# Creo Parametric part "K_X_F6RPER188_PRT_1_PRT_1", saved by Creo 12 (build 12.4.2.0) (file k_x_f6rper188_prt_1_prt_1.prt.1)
Units: Custom; MM, KILOGRAM, SECS

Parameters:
  PTC_WM_ITERATION = "0"
  PTC_WM_VERSION = "-.0"
  PTC_WM_LIFECYCLE_STATE = "In Work"
  PTC_WM_LIFECYCLE = "MO_CADDocument"
  PTC_WM_CREATED_BY = "Maximilian Roepper (Z0017RMS: MO)"
  PTC_WM_CREATED_ON = "18-Sep-26 11:36:42 AM"
  PTC_WM_MODIFIED_BY = "Maximilian Roepper (Z0017RMS: MO)"
  PTC_WM_MODIFIED_ON = "18-Sep-26 11:36:46 AM"
  PDMLINKNUMBER = "PDM000071455099"
  PTC_WM_NAME = "k_x_f6rper188_prt_1_prt_1.prt"
  PTC_WM_NUMBER = "PDM000071455099"

Other parameters: WEIGHT, WEIGHT_FACTOR, WEIGHT_ADD, _MASS_TEMP, _DIFF_TEMP, MC_ERRORS, SUPPLIER

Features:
  1. coordinate system
  2. datum plane "PRT_YZ"
  3. datum plane "PRT_XY"
  4. datum plane "PRT_XZ"
  5. coordinate system
  6. datum axis
  7. datum axis
  8. datum axis
  9. coordinate system
  10. imported feature
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
Other named items: PRT, SIEMENS_MO, DRW_VIEW_ORG, PRT_X, PRT_Y, PRT_Z, CS0, ROUGH_GROB

Layers: 00_STD_CSYS-KSYS, 01_STD_PLANES-EBENEN, 02_STD_AXES-ACHSEN, 03_STD_CSYS-KSYS, 24_IMPORT_FEAT-IMPORT_KE

Surfaces: 20 tabulated cylinder, 4 plane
